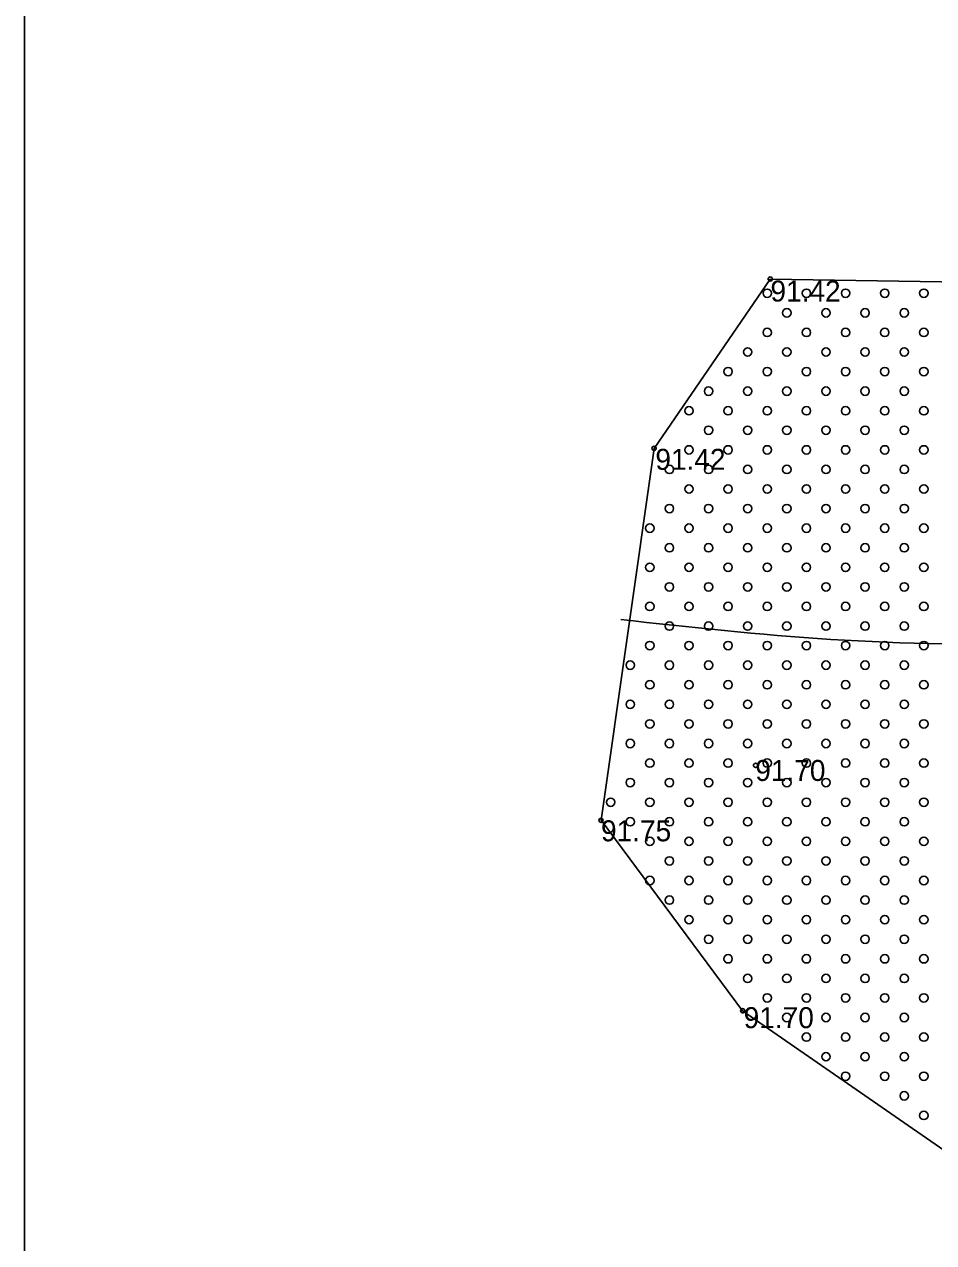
# Model space of a CAD drawing. Extents: x 316000 to 728450, y 314368 to 726000.
# Drawn here: x 725371.7 to 725534.2, y 315232.8 to 315450.6 of the extents above; entities that cross this region are included whole.
import ezdxf

# ---------------------------------------------------------------- set-up
doc = ezdxf.new("R2010")
doc.units = 0
for name, color, linetype in [('RAMI_PLAN_####_TKST_#', 7, 'Continuous'), ('RAMI_UZMR_####_####_#', 7, 'Continuous'), ('RELJ_AATZ_####_TKST_#', 7, 'Continuous'), ('RELJ_ELEM_####_####_#', 7, 'Continuous'), ('RELJ_HORZ_PAMT_####_#', 7, 'Continuous'), ('TERT_ELEM_####_####_#', 7, 'Continuous')]:
    doc.layers.add(name, color=color, linetype=linetype)

msp = doc.modelspace()

# ---------------------------------------------------------------- linework, layer by layer
at = {"layer": 'RAMI_PLAN_####_TKST_#'}
msp.add_lwpolyline([(725371.66, 314368.28), (727955.92, 314368.28), (727955.92, 316766.42), (725371.66, 316766.42)], close=True, dxfattribs=at)
at = {"layer": 'RAMI_UZMR_####_####_#'}
msp.add_lwpolyline([(727254.69, 315085.95), (727002.7, 315002.84), (726508.21, 314868.03), (726416.7, 314837.05), (725982.38, 314530.96), (725916.44, 314513.26), (725799.16, 314549.2), (725735.9, 314623.63), (725701.82, 314711.1), (725697.25, 315112.64), (725659.91, 315163.35), (725614.81, 315211.65), (725561.8, 315231.45), (725500.09, 315274.21), (725474.77, 315308.26), (725484.26, 315374.77), (725505.03, 315405.04), (725554.87, 315404.25), (725559.14, 315567.14), (725558.67, 315591.68), (725662, 315676.73), (726089.69, 315915.19)], dxfattribs=at)
at = {"layer": 'RELJ_ELEM_####_####_#'}
for centre in [(725505.03, 315405.04), (725484.26, 315374.77), (725502.41, 315318.1), (725474.77, 315308.26), (725500.09, 315274.21)]:
    msp.add_circle(centre, 0.375, dxfattribs=at)
at = {"layer": 'RELJ_HORZ_PAMT_####_#'}
msp.add_spline([(726081.57, 315247.05), (726057.5, 315241.5), (726036.5, 315213.5), (725977, 315161), (725966.5, 315108.5), (725903.5, 315045.5), (725862.12, 315076.6), (725805.5, 315130), (725759.7, 315178.88), (725709.89, 315228.8), (725646.99, 315287.19), (725634.68, 315314.96), (725629.04, 315327.48), (725557.35, 315340.26), (725478.3, 315344.16)], degree=3, dxfattribs=at)
at = {"layer": 'TERT_ELEM_####_####_#'}
for centre in [(725504.5, 315402.5), (725511.5, 315402.5), (725518.5, 315402.5), (725525.5, 315402.5), (725532.5, 315402.5), (725508, 315399), (725515, 315399), (725522, 315399), (725529, 315399), (725504.5, 315395.5), (725511.5, 315395.5), (725518.5, 315395.5), (725525.5, 315395.5), (725532.5, 315395.5), (725501, 315392), (725508, 315392), (725515, 315392), (725522, 315392), (725529, 315392), (725497.5, 315388.5), (725504.5, 315388.5), (725511.5, 315388.5), (725518.5, 315388.5), (725525.5, 315388.5), (725532.5, 315388.5), (725494, 315385), (725501, 315385), (725508, 315385), (725515, 315385), (725522, 315385), (725529, 315385), (725490.5, 315381.5), (725497.5, 315381.5), (725504.5, 315381.5), (725511.5, 315381.5), (725518.5, 315381.5), (725525.5, 315381.5), (725532.5, 315381.5), (725494, 315378), (725501, 315378), (725508, 315378), (725515, 315378), (725522, 315378), (725529, 315378), (725490.5, 315374.5), (725497.5, 315374.5), (725504.5, 315374.5), (725511.5, 315374.5), (725518.5, 315374.5), (725525.5, 315374.5), (725532.5, 315374.5), (725487, 315371), (725494, 315371), (725501, 315371), (725508, 315371), (725515, 315371), (725522, 315371), (725529, 315371), (725490.5, 315367.5), (725497.5, 315367.5), (725504.5, 315367.5), (725511.5, 315367.5), (725518.5, 315367.5), (725525.5, 315367.5), (725532.5, 315367.5), (725487, 315364), (725494, 315364), (725501, 315364), (725508, 315364), (725515, 315364), (725522, 315364), (725529, 315364), (725483.5, 315360.5), (725490.5, 315360.5), (725497.5, 315360.5), (725504.5, 315360.5), (725511.5, 315360.5), (725518.5, 315360.5), (725525.5, 315360.5), (725532.5, 315360.5), (725487, 315357), (725494, 315357), (725501, 315357), (725508, 315357), (725515, 315357), (725522, 315357), (725529, 315357), (725483.5, 315353.5), (725490.5, 315353.5), (725497.5, 315353.5), (725504.5, 315353.5), (725511.5, 315353.5), (725518.5, 315353.5), (725525.5, 315353.5), (725532.5, 315353.5), (725487, 315350), (725494, 315350), (725501, 315350), (725508, 315350), (725515, 315350), (725522, 315350), (725529, 315350), (725483.5, 315346.5), (725490.5, 315346.5), (725497.5, 315346.5), (725504.5, 315346.5), (725511.5, 315346.5), (725518.5, 315346.5), (725525.5, 315346.5), (725532.5, 315346.5), (725487, 315343), (725494, 315343), (725501, 315343), (725508, 315343), (725515, 315343), (725522, 315343), (725529, 315343), (725483.5, 315339.5), (725490.5, 315339.5), (725497.5, 315339.5), (725504.5, 315339.5), (725511.5, 315339.5), (725518.5, 315339.5), (725525.5, 315339.5), (725532.5, 315339.5), (725480, 315336), (725487, 315336), (725494, 315336), (725501, 315336), (725508, 315336), (725515, 315336), (725522, 315336), (725529, 315336), (725483.5, 315332.5), (725490.5, 315332.5), (725497.5, 315332.5), (725504.5, 315332.5), (725511.5, 315332.5), (725518.5, 315332.5), (725525.5, 315332.5), (725532.5, 315332.5), (725480, 315329), (725487, 315329), (725494, 315329), (725501, 315329), (725508, 315329), (725515, 315329), (725522, 315329), (725529, 315329), (725483.5, 315325.5), (725490.5, 315325.5), (725497.5, 315325.5), (725504.5, 315325.5), (725511.5, 315325.5), (725518.5, 315325.5), (725525.5, 315325.5), (725532.5, 315325.5), (725480, 315322), (725487, 315322), (725494, 315322), (725501, 315322), (725508, 315322), (725515, 315322), (725522, 315322), (725529, 315322), (725483.5, 315318.5), (725490.5, 315318.5), (725497.5, 315318.5), (725504.5, 315318.5), (725511.5, 315318.5), (725518.5, 315318.5), (725525.5, 315318.5), (725532.5, 315318.5), (725480, 315315), (725487, 315315), (725494, 315315), (725501, 315315), (725508, 315315), (725515, 315315), (725522, 315315), (725529, 315315), (725476.5, 315311.5), (725483.5, 315311.5), (725490.5, 315311.5), (725497.5, 315311.5), (725504.5, 315311.5), (725511.5, 315311.5), (725518.5, 315311.5), (725525.5, 315311.5), (725532.5, 315311.5), (725480, 315308), (725487, 315308), (725494, 315308), (725501, 315308), (725508, 315308), (725515, 315308), (725522, 315308), (725529, 315308), (725483.5, 315304.5), (725490.5, 315304.5), (725497.5, 315304.5), (725504.5, 315304.5), (725511.5, 315304.5), (725518.5, 315304.5), (725525.5, 315304.5), (725532.5, 315304.5), (725487, 315301), (725494, 315301), (725501, 315301), (725508, 315301), (725515, 315301), (725522, 315301), (725529, 315301), (725483.5, 315297.5), (725490.5, 315297.5), (725497.5, 315297.5), (725504.5, 315297.5), (725511.5, 315297.5), (725518.5, 315297.5), (725525.5, 315297.5), (725532.5, 315297.5), (725487, 315294), (725494, 315294), (725501, 315294), (725508, 315294), (725515, 315294), (725522, 315294), (725529, 315294), (725490.5, 315290.5), (725497.5, 315290.5), (725504.5, 315290.5), (725511.5, 315290.5), (725518.5, 315290.5), (725525.5, 315290.5), (725532.5, 315290.5), (725494, 315287), (725501, 315287), (725508, 315287), (725515, 315287), (725522, 315287), (725529, 315287), (725497.5, 315283.5), (725504.5, 315283.5), (725511.5, 315283.5), (725518.5, 315283.5), (725525.5, 315283.5), (725532.5, 315283.5), (725501, 315280), (725508, 315280), (725515, 315280), (725522, 315280), (725529, 315280), (725504.5, 315276.5), (725511.5, 315276.5), (725518.5, 315276.5), (725525.5, 315276.5), (725532.5, 315276.5), (725508, 315273), (725515, 315273), (725522, 315273), (725529, 315273), (725511.5, 315269.5), (725518.5, 315269.5), (725525.5, 315269.5), (725532.5, 315269.5), (725515, 315266), (725522, 315266), (725529, 315266), (725518.5, 315262.5), (725525.5, 315262.5), (725532.5, 315262.5), (725529, 315259), (725532.5, 315255.5)]:
    msp.add_circle(centre, 0.75, dxfattribs=at)

# ---------------------------------------------------------------- texts
at = {"layer": 'RELJ_AATZ_####_TKST_#'}
for s, p in [('91.42', (725505.07, 315401.02)), ('91.42', (725484.49, 315370.93)), ('91.70', (725502.36, 315315.3)), ('91.75', (725474.77, 315304.51)), ('91.70', (725500.28, 315271.1))]:
    msp.add_text(s, height=3.75, dxfattribs=at).set_placement(p)

doc.saveas('drawing.dxf')
